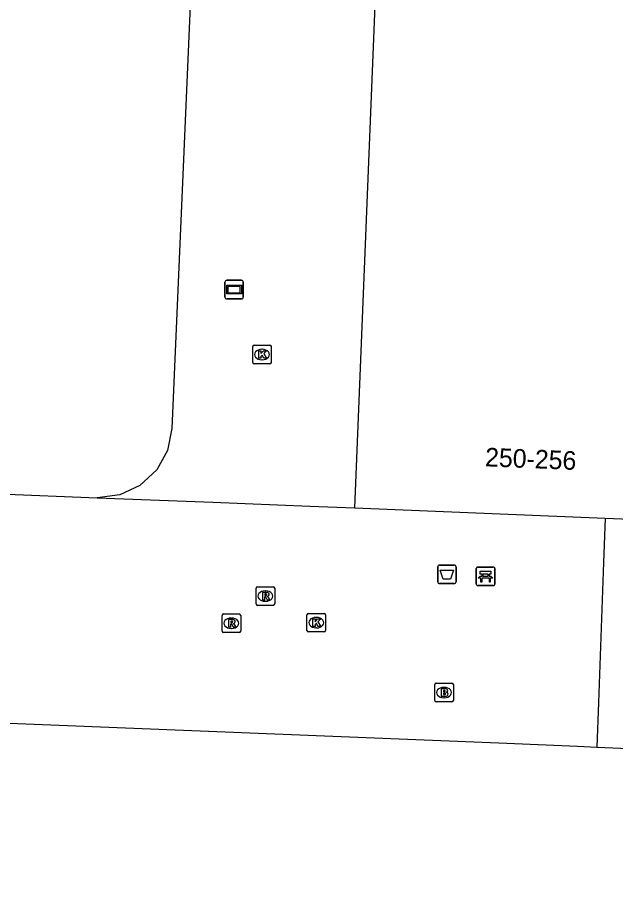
# Model space of a CAD drawing. Extents: x 160891 to 161384, y 386490 to 386907.
# Drawn here: x 161173.06 to 161205.21, y 386547.89 to 386595.38 of the extents above; entities that cross this region are included whole.
import ezdxf

# ---------------------------------------------------------------- set-up
doc = ezdxf.new("R2010")
doc.units = 0
for name, color, linetype in [('IMGEO_Afvalbak', 7, 'Continuous'), ('IMGEO_Bank', 7, 'Continuous'), ('IMGEO_Brandkraan', 7, 'Continuous'), ('IMGEO_Hek', 7, 'Continuous'), ('IMGEO_Kolk', 7, 'Continuous'), ('IMGEO_Pand', 7, 'Continuous'), ('IMGEO_Pand_nummerreeks', 7, 'Continuous'), ('IMGEO_Reclamebord', 7, 'Continuous'), ('IMGEO_Rioolput', 7, 'Continuous'), ('IMGEO_Voetgangersgebied_open', 7, 'Continuous')]:
    doc.layers.add(name, color=color, linetype=linetype)

msp = doc.modelspace()

# ---------------------------------------------------------------- linework, layer by layer
at = {"layer": 'IMGEO_Afvalbak'}
for p, q in [((161195.655, 386565.033), (161195.655, 386565.833)), ((161195.655, 386565.833), (161195.655, 386565.033)), ((161195.755, 386565.933), (161196.545, 386565.933)), ((161196.545, 386565.933), (161195.755, 386565.933)), ((161196.645, 386565.833), (161196.645, 386565.033)), ((161196.645, 386565.033), (161196.645, 386565.833)), ((161196.545, 386564.933), (161195.755, 386564.933)), ((161195.755, 386564.933), (161196.545, 386564.933))]:
    msp.add_line(p, q, dxfattribs=at)
msp.add_lwpolyline([(161195.798, 386565.647), (161196.502, 386565.647), (161196.353, 386565.177), (161195.947, 386565.177), (161195.798, 386565.647)], dxfattribs=at)
for centre, start, end in [((161195.755, 386565.833), 90, 180), ((161195.755, 386565.833), 90, 180), ((161196.545, 386565.833), 0, 90), ((161196.545, 386565.833), 360, 90), ((161195.755, 386565.033), 180, 270), ((161195.755, 386565.033), 180, 270), ((161196.545, 386565.033), 270, 0), ((161196.545, 386565.033), 270, 0)]:
    msp.add_arc(centre, 0.1, start, end, dxfattribs=at)
at = {"layer": 'IMGEO_Bank'}
for p, q in [((161197.732, 386564.9), (161197.732, 386565.741)), ((161197.732, 386565.741), (161197.732, 386564.9)), ((161197.807, 386565.825), (161198.648, 386565.825)), ((161198.648, 386565.825), (161197.807, 386565.825)), ((161198.732, 386565.75), (161198.732, 386564.909)), ((161198.732, 386564.909), (161198.732, 386565.75)), ((161198.041, 386565.331), (161198.041, 386565.437)), ((161198.085, 386565.437), (161198.085, 386565.331)), ((161198.373, 386565.443), (161198.091, 386565.443)), ((161198.091, 386565.325), (161198.373, 386565.325)), ((161198.379, 386565.331), (161198.379, 386565.437)), ((161198.423, 386565.437), (161198.423, 386565.331)), ((161198.657, 386564.825), (161197.816, 386564.825)), ((161197.816, 386564.825), (161198.657, 386564.825)), ((161198.429, 386565.223), (161198.036, 386565.223))]:
    msp.add_line(p, q, dxfattribs=at)
for points in [[(161197.979, 386565.223), (161197.837, 386565.223), (161197.949, 386565.325), (161198.035, 386565.325)], [(161198.035, 386565.443), (161197.949, 386565.443), (161197.949, 386565.604), (161198.512, 386565.604), (161198.512, 386565.443), (161198.429, 386565.443)], [(161198.429, 386565.325), (161198.512, 386565.325), (161198.624, 386565.223), (161198.485, 386565.223)], [(161198.029, 386565.216), (161198.029, 386565.009), (161197.986, 386565.009), (161197.986, 386565.216)], [(161198.479, 386565.216), (161198.479, 386565.009), (161198.435, 386565.009), (161198.435, 386565.216)]]:
    msp.add_lwpolyline(points, dxfattribs=at)
for centre, radius, start, end in [((161197.81, 386565.747), 0.0779, 92.4484, 184.2845), ((161197.81, 386565.747), 0.0779, 92.4484, 184.2845), ((161198.654, 386565.747), 0.0779, 2.4484, 94.2845), ((161198.654, 386565.747), 0.0779, 2.4484, 94.2845), ((161198.034, 386565.436), 0.00671, 2.8957, 87.1043), ((161198.034, 386565.332), 0.00671, 272.8957, 357.1043), ((161198.091, 386565.436), 0.00671, 92.8957, 177.1043), ((161198.091, 386565.332), 0.00671, 182.8957, 267.1043), ((161198.373, 386565.436), 0.00671, 2.8957, 87.1043), ((161198.373, 386565.332), 0.00671, 272.8957, 357.1043), ((161198.43, 386565.436), 0.00671, 92.8957, 177.1043), ((161198.43, 386565.332), 0.00671, 182.8957, 267.1043), ((161197.81, 386564.903), 0.0779, 182.4484, 274.2845), ((161197.81, 386564.903), 0.0779, 182.4484, 274.2845), ((161197.979, 386565.216), 0.00671, 2.8957, 87.1043), ((161198.036, 386565.216), 0.00671, 92.8957, 177.1043), ((161198.428, 386565.216), 0.00671, 2.8957, 87.1043), ((161198.485, 386565.216), 0.00671, 92.8957, 177.1043), ((161198.654, 386564.903), 0.0779, 272.4484, 4.2845), ((161198.654, 386564.903), 0.0779, 272.4484, 4.2845)]:
    msp.add_arc(centre, radius, start, end, dxfattribs=at)
at = {"layer": 'IMGEO_Brandkraan'}
for p, q in [((161195.572, 386559.571), (161196.424, 386559.571)), ((161195.497, 386558.645), (161195.497, 386559.497)), ((161195.985, 386559.351), (161196.01, 386559.351)), ((161196.498, 386559.497), (161196.498, 386558.645)), ((161196.008, 386558.791), (161195.983, 386558.791)), ((161196.424, 386558.571), (161195.572, 386558.571))]:
    msp.add_line(p, q, dxfattribs=at)
for points in [[(161195.572, 386559.571), (161196.424, 386559.571)], [(161195.497, 386558.645), (161195.497, 386559.497)], [(161195.845, 386559.271), (161195.845, 386558.871), (161196.058, 386558.871)], [(161196.076, 386559.271), (161195.845, 386559.271)], [(161196.024, 386559.19), (161195.97, 386559.19), (161195.97, 386559.114)], [(161195.97, 386559.114), (161196.023, 386559.114)], [(161196.498, 386559.497), (161196.498, 386558.645)], [(161196.032, 386559.038), (161195.97, 386559.038), (161195.97, 386558.957)], [(161195.97, 386558.957), (161196.032, 386558.957)], [(161196.424, 386558.571), (161195.572, 386558.571)]]:
    msp.add_lwpolyline(points, dxfattribs=at)
for centre, radius, start, end in [((161195.574, 386559.495), 0.0765, 91.552, 178.448), ((161195.574, 386559.495), 0.0765, 91.552, 178.448), ((161196.422, 386559.495), 0.0765, 1.552, 88.448), ((161196.422, 386559.495), 0.0765, 1.552, 88.448), ((161196.025, 386559.152), 0.0379, 267.8285, 90.9355), ((161196.08, 386559.126), 0.145, 59.4692, 91.5367), ((161196.105, 386559.173), 0.0922, 285.5137, 58.1501), ((161195.574, 386558.647), 0.0765, 181.552, 268.448), ((161195.574, 386558.647), 0.0765, 181.552, 268.448), ((161196.033, 386558.997), 0.0404, 269.8759, 90.5077), ((161196.064, 386559.122), 0.251, 268.6676, 293.5347), ((161196.11, 386558.981), 0.105, 301.3115, 78.989), ((161196.422, 386558.647), 0.0765, 271.552, 358.448), ((161196.422, 386558.647), 0.0765, 271.552, 358.448)]:
    msp.add_arc(centre, radius, start, end, dxfattribs=at)
for centre, major_axis, ratio, start_param, end_param in [((161195.984, 386559.071), (-0.387, 0.002), 0.722429, 4.712389, 7.853982), ((161196.009, 386559.071), (-0.39, 0.002), 0.717154, 1.570796, 4.712389)]:
    msp.add_ellipse(centre, major_axis=major_axis, ratio=ratio, start_param=start_param, end_param=end_param, dxfattribs=at)
at = {"layer": 'IMGEO_Hek'}
for points in [[(161204.671, 386568.461), (161204.584, 386566.069)], [(161204.584, 386566.069), (161204.309, 386558.529)], [(161204.309, 386558.529), (161204.222, 386556.138)]]:
    msp.add_lwpolyline(points, dxfattribs=at)
at = {"layer": 'IMGEO_Kolk'}
for p, q in [((161185.705, 386576.832), (161185.705, 386577.684)), ((161185.78, 386577.758), (161186.632, 386577.758)), ((161186.706, 386577.684), (161186.706, 386576.832)), ((161186.193, 386577.538), (161186.218, 386577.538)), ((161186.632, 386576.758), (161185.78, 386576.758)), ((161186.216, 386576.978), (161186.191, 386576.978)), ((161188.623, 386562.406), (161188.623, 386563.258)), ((161188.698, 386563.332), (161189.55, 386563.332)), ((161189.111, 386563.112), (161189.136, 386563.112)), ((161189.624, 386563.258), (161189.624, 386562.406)), ((161189.134, 386562.552), (161189.109, 386562.552)), ((161189.55, 386562.332), (161188.698, 386562.332))]:
    msp.add_line(p, q, dxfattribs=at)
for points in [[(161185.705, 386576.832), (161185.705, 386577.684)], [(161185.78, 386577.758), (161186.632, 386577.758)], [(161186.706, 386577.684), (161186.706, 386576.832)], [(161186.026, 386577.458), (161186.149, 386577.458), (161186.149, 386577.307), (161186.279, 386577.458), (161186.443, 386577.458), (161186.297, 386577.307), (161186.45, 386577.058), (161186.298, 386577.058), (161186.213, 386577.222), (161186.149, 386577.155), (161186.149, 386577.058), (161186.026, 386577.058), (161186.026, 386577.458)], [(161186.632, 386576.758), (161185.78, 386576.758)], [(161188.623, 386562.406), (161188.623, 386563.258)], [(161188.698, 386563.332), (161189.55, 386563.332)], [(161188.944, 386563.032), (161189.067, 386563.032), (161189.067, 386562.881), (161189.197, 386563.032), (161189.361, 386563.032), (161189.215, 386562.881), (161189.368, 386562.632), (161189.216, 386562.632), (161189.131, 386562.796), (161189.067, 386562.729), (161189.067, 386562.632), (161188.944, 386562.632), (161188.944, 386563.032)], [(161189.624, 386563.258), (161189.624, 386562.406)], [(161189.55, 386562.332), (161188.698, 386562.332)]]:
    msp.add_lwpolyline(points, dxfattribs=at)
for centre, start, end in [((161185.782, 386577.682), 91.552, 178.448), ((161185.782, 386577.682), 91.552, 178.448), ((161186.63, 386577.682), 1.552, 88.448), ((161186.63, 386577.682), 1.552, 88.448), ((161185.782, 386576.834), 181.552, 268.448), ((161185.782, 386576.834), 181.552, 268.448), ((161186.63, 386576.834), 271.552, 358.448), ((161186.63, 386576.834), 271.552, 358.448), ((161188.7, 386563.256), 91.552, 178.448), ((161188.7, 386563.256), 91.552, 178.448), ((161189.548, 386563.256), 1.552, 88.448), ((161189.548, 386563.256), 1.552, 88.448), ((161188.7, 386562.408), 181.552, 268.448), ((161188.7, 386562.408), 181.552, 268.448), ((161189.548, 386562.408), 271.552, 358.448), ((161189.548, 386562.408), 271.552, 358.448)]:
    msp.add_arc(centre, 0.0765, start, end, dxfattribs=at)
for centre, major_axis, ratio, start_param, end_param in [((161186.192, 386577.258), (-0.387, 0.002), 0.722429, 4.712389, 7.853982), ((161186.217, 386577.258), (-0.39, 0.002), 0.717154, 1.570796, 4.712389), ((161189.11, 386562.832), (-0.387, 0.002), 0.722429, 4.712389, 7.853982), ((161189.135, 386562.832), (-0.39, 0.002), 0.717154, 1.570796, 4.712389)]:
    msp.add_ellipse(centre, major_axis=major_axis, ratio=ratio, start_param=start_param, end_param=end_param, dxfattribs=at)
at = {"layer": 'IMGEO_Pand'}
for points in [[(161183.781, 386706.174), (161184.602, 386705.296), (161185.308, 386704.253), (161185.839, 386703.176), (161186.212, 386702.035), (161186.412, 386700.854), (161186.449, 386699.801), (161184.541, 386652.073), (161184.503, 386648.738), (161165.034, 386649.524), (161165.981, 386672.875), (161161.964, 386673.038), (161158.269, 386582.057), (161162.285, 386581.893), (161163.18, 386603.875), (161182.646, 386603.083), (161181.347, 386573.278), (161181.119, 386572.09), (161180.548, 386571.054), (161179.639, 386570.209), (161178.554, 386569.701), (161177.328, 386569.555)], [(161191.198, 386569.006), (161192.541, 386602.265), (161192.441, 386602.269), (161192.456, 386602.678), (161214.141, 386601.806)], [(161191.198, 386569.006), (161204.671, 386568.461), (161212.673, 386568.138), (161213.252, 386579.772), (161213.556, 386587.296)], [(161143.412, 386571.685), (161144.419, 386571.089), (161145.572, 386570.831), (161177.328, 386569.555)], [(161202.016, 386541.511), (161183.318, 386542.275), (161183.23, 386540.097), (161161.956, 386540.961), (161144.595, 386541.66), (161143.172, 386541.779), (161142.962, 386541.796), (161141.573, 386541.866), (161142.239, 386558.637), (161198.944, 386556.36), (161203.171, 386556.182), (161204.222, 386556.138), (161265.583, 386553.546), (161265.022, 386539.386), (161265.122, 386539.382), (161265.105, 386538.962), (161255.052, 386539.373), (161255.062, 386539.613), (161240.655, 386540.207), (161240.646, 386539.967), (161226.27, 386540.547), (161207.362, 386541.287)]]:
    msp.add_lwpolyline(points, dxfattribs=at)
at = {"layer": 'IMGEO_Reclamebord'}
for p, q in [((161184.209, 386580.351), (161184.209, 386581.151)), ((161184.209, 386581.151), (161184.209, 386580.351)), ((161184.309, 386581.251), (161185.099, 386581.251)), ((161185.099, 386581.251), (161184.309, 386581.251)), ((161185.199, 386581.151), (161185.199, 386580.351)), ((161185.199, 386580.351), (161185.199, 386581.151)), ((161185.099, 386580.251), (161184.309, 386580.251)), ((161184.309, 386580.251), (161185.099, 386580.251))]:
    msp.add_line(p, q, dxfattribs=at)
for points in [[(161184.31, 386580.983), (161185.098, 386580.983), (161185.098, 386580.519), (161184.31, 386580.519), (161184.31, 386580.983)], [(161184.375, 386580.918), (161184.375, 386580.584), (161185.033, 386580.584), (161185.033, 386580.918), (161184.375, 386580.918)]]:
    msp.add_lwpolyline(points, dxfattribs=at)
for centre, start, end in [((161184.309, 386581.151), 90, 180), ((161184.309, 386581.151), 90, 180), ((161185.099, 386581.151), 0, 90), ((161185.099, 386581.151), 360, 90), ((161184.309, 386580.351), 180, 270), ((161184.309, 386580.351), 180, 270), ((161185.099, 386580.351), 270, 0), ((161185.099, 386580.351), 270, 0)]:
    msp.add_arc(centre, 0.1, start, end, dxfattribs=at)
at = {"layer": 'IMGEO_Rioolput'}
for p, q in [((161185.888, 386563.836), (161185.888, 386564.688)), ((161185.963, 386564.762), (161186.815, 386564.762)), ((161186.376, 386564.542), (161186.401, 386564.542)), ((161186.889, 386564.688), (161186.889, 386563.836)), ((161186.399, 386563.982), (161186.374, 386563.982)), ((161186.815, 386563.762), (161185.963, 386563.762)), ((161184.059, 386562.373), (161184.059, 386563.225)), ((161184.134, 386563.299), (161184.986, 386563.299)), ((161184.547, 386563.079), (161184.572, 386563.079)), ((161185.06, 386563.225), (161185.06, 386562.373)), ((161184.57, 386562.519), (161184.545, 386562.519)), ((161184.986, 386562.299), (161184.134, 386562.299))]:
    msp.add_line(p, q, dxfattribs=at)
for points in [[(161185.888, 386563.836), (161185.888, 386564.688)], [(161185.963, 386564.762), (161186.815, 386564.762)], [(161186.477, 386564.46), (161186.225, 386564.462), (161186.225, 386564.062)], [(161186.403, 386564.381), (161186.349, 386564.381), (161186.349, 386564.3)], [(161186.889, 386564.688), (161186.889, 386563.836)], [(161186.225, 386564.062), (161186.349, 386564.062), (161186.349, 386564.224), (161186.36, 386564.224)], [(161186.349, 386564.3), (161186.401, 386564.3)], [(161186.407, 386564.195), (161186.478, 386564.062), (161186.618, 386564.062), (161186.553, 386564.188)], [(161186.815, 386563.762), (161185.963, 386563.762)], [(161184.059, 386562.373), (161184.059, 386563.225)], [(161184.134, 386563.299), (161184.986, 386563.299)], [(161184.648, 386562.997), (161184.396, 386562.999), (161184.396, 386562.599)], [(161184.574, 386562.918), (161184.52, 386562.918), (161184.52, 386562.837)], [(161185.06, 386563.225), (161185.06, 386562.373)], [(161184.396, 386562.599), (161184.52, 386562.599), (161184.52, 386562.761), (161184.531, 386562.761)], [(161184.52, 386562.837), (161184.572, 386562.837)], [(161184.578, 386562.732), (161184.649, 386562.599), (161184.789, 386562.599), (161184.724, 386562.725)], [(161184.986, 386562.299), (161184.134, 386562.299)]]:
    msp.add_lwpolyline(points, dxfattribs=at)
for centre, radius, start, end in [((161185.965, 386564.686), 0.0765, 91.552, 178.448), ((161185.965, 386564.686), 0.0765, 91.552, 178.448), ((161186.409, 386564.285), 0.0964, 77.0061, 93.1865), ((161186.423, 386564.342), 0.0378, 276.6634, 79.6772), ((161186.476, 386564.35), 0.109, 350.3612, 89.416), ((161186.474, 386564.35), 0.112, 277.5842, 350.9817), ((161186.813, 386564.686), 0.0765, 1.552, 88.448), ((161186.813, 386564.686), 0.0765, 1.552, 88.448), ((161186.359, 386564.171), 0.0533, 26.0293, 88.6989), ((161186.385, 386564.489), 0.19, 274.7715, 282.9687), ((161186.458, 386564.135), 0.108, 29.5134, 73.7905), ((161185.965, 386563.838), 0.0765, 181.552, 268.448), ((161185.965, 386563.838), 0.0765, 181.552, 268.448), ((161186.813, 386563.838), 0.0765, 271.552, 358.448), ((161186.813, 386563.838), 0.0765, 271.552, 358.448), ((161184.136, 386563.223), 0.0765, 91.552, 178.448), ((161184.136, 386563.223), 0.0765, 91.552, 178.448), ((161184.58, 386562.822), 0.0964, 77.0061, 93.1865), ((161184.594, 386562.879), 0.0378, 276.6634, 79.6772), ((161184.647, 386562.887), 0.109, 350.3612, 89.416), ((161184.984, 386563.223), 0.0765, 1.552, 88.448), ((161184.984, 386563.223), 0.0765, 1.552, 88.448), ((161184.53, 386562.708), 0.0533, 26.0293, 88.6989), ((161184.556, 386563.026), 0.19, 274.7715, 282.9687), ((161184.645, 386562.887), 0.112, 277.5842, 350.9817), ((161184.629, 386562.672), 0.108, 29.5134, 73.7905), ((161184.136, 386562.375), 0.0765, 181.552, 268.448), ((161184.136, 386562.375), 0.0765, 181.552, 268.448), ((161184.984, 386562.375), 0.0765, 271.552, 358.448), ((161184.984, 386562.375), 0.0765, 271.552, 358.448)]:
    msp.add_arc(centre, radius, start, end, dxfattribs=at)
for centre, major_axis, ratio, start_param, end_param in [((161186.375, 386564.262), (-0.387, 0.002), 0.722429, 4.712389, 7.853982), ((161186.4, 386564.262), (-0.39, 0.002), 0.717154, 1.570796, 4.712389), ((161184.546, 386562.799), (-0.387, 0.002), 0.722429, 4.712389, 7.853982), ((161184.571, 386562.799), (-0.39, 0.002), 0.717154, 1.570796, 4.712389)]:
    msp.add_ellipse(centre, major_axis=major_axis, ratio=ratio, start_param=start_param, end_param=end_param, dxfattribs=at)
at = {"layer": 'IMGEO_Voetgangersgebied_open'}
msp.add_lwpolyline([(161177.328, 386569.555), (161183.563, 386569.308), (161188.786, 386569.101), (161191.198, 386569.006)], dxfattribs=at)

# ---------------------------------------------------------------- texts
at = {"layer": 'IMGEO_Pand_nummerreeks'}
msp.add_text('250-256', height=1, rotation=357.6854, dxfattribs=at).set_placement((161198.191, 386571.245))

doc.saveas('drawing.dxf')
